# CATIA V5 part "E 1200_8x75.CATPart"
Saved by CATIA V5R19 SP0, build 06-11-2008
Definition: E 1200_8x75
Nomenclature: E 1200_8x75
Description: PART--DESC
Material "Steel": density 7860 kg/m3, Young's modulus 2e+11 Pa, Poisson ratio 0.266, thermal expansion 1.17e-05 1/K
Bounding box of the stored display mesh (mm): x 160.51 to 173.49, y -98 to -85, z 10.5 to 93.5
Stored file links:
  G:\UTB\Kombinované\Bakalářská práce\Catia\FORMA\E 1200_8x75.CATPart
  D:\Aplikace\CATIA\Nová složka\win_b64\startup\materials\Catalog.CATMaterial
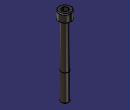
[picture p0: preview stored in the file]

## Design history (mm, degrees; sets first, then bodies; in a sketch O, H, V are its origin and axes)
Body1 "E 1200_8x75" (main body)
  Solid1: solid without history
